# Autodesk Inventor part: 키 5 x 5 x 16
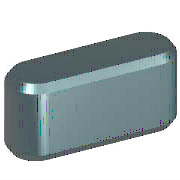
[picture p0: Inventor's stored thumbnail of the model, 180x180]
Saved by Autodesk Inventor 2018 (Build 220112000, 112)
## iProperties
IsCustomPart: 1
Created: 2012-02
Part Number: 키 5 x 5 x 16
Material: 강철, 연강
Description: 키 및 해당 키홈
Document SubType Name: Modeling
Standard: KS B 1311
Designer: mduedu
Standards Organization: KS
Language: ko-KR
Size Designation: 5 x 5 x 16
Categories: <MemberInstance><Categories><Category DisplayName="샤프트 부품" InternalName="7f7aeb1f-a693-4053-b835-cee3144e0d98" Mnemonic="SHFT"><Category DisplayName="키" Interna
Density: 1 g/cm^3
Appearance: 노란색
Author: mduedu
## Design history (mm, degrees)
workplane "Work Plane1"
workplane "Work Plane2"
sketch "스케치1"
  geometry: L1 (2.5, 2.5)-(13.5, 2.5); L2 (13.5, -2.5)-(2.5, -2.5); L3 (0, 9.4)-(0, -7.4) reference; L4 (-5, 0)-(30, 0) reference; L5 (16, 0)-(16, 7); A1 r 2.5 centre (2.5, 0) between (2.5, 2.5) and (2.5, -2.5); A2 r 2.5 centre (13.5, 0) between (13.5, -2.5) and (13.5, 2.5)
  constraints: 6 end point, 5 point on circle, 4 tangent, 3 point on line, 2 centre point, 1 horizontal, 1 parallel, 1 perpendicular
  dimensions: "d0" = 2.5 radius of A1 (= 0.5 x PB); "d13" = 2.5 radius of A2 (= 0.5 x PB); "d14" = 16 distance between parallel lines of L5 L3 (= NLG)
extrude "본체1" new body sketch "스케치1" taper "d3" = 0 deg; stored distance "d4" = 10
workplane "Work Plane3"
body "Solid1"
chamfer "모따기1" distance "d8" = 0.4 (= PHH); stored, may be unused: second distance "d9" = 0.4 (= PHH), angle "d15" = 45 deg
other parameters: "d1" = -3 (= -PNT), "d2" = 2 (= PH - PNT), "NLG" = 16 [user parameter; used in 3 equation terms], "PB" = 5 [user parameter; used in 2 equation terms], "PNT" = 3 [user parameter; used in 2 equation terms], "PH" = 5 [user parameter; used in 1 equation term], "PHH" = 0.4 [user parameter; used in 2 equation terms], "d10" = 0, "d16" = 0, "d17" = 0, "d18" = 0, "WDMIN" = 12 [user parameter], "PLB2" = 16 (= NLG) [user parameter], "WDMAX" = 17 [user parameter], "PLB1" = 16 (= NLG) [user parameter], "RR" = 0.16 [user parameter], "PUEB" = 2.3 [user parameter]
